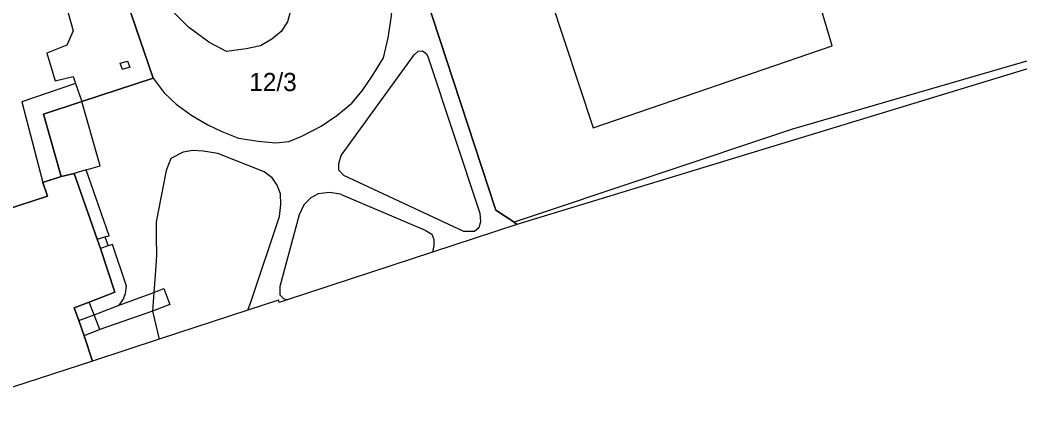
# Model space of a CAD drawing. Extents: x -264070 to -262271, y -1238894 to -1238141.
# Drawn here: x -263238.5 to -263128.8, y -1238889.7 to -1238845.2 of the extents above; entities that cross this region are included whole.
import ezdxf

# ---------------------------------------------------------------- set-up
doc = ezdxf.new("R2010")
doc.units = 0
for name, color, linetype in [('body_kn', 7, 'Continuous'), ('katuz_linie', 7, 'Continuous'), ('kladpar_druhypozemkov', 7, 'Continuous'), ('kladpar_hranice', 7, 'Continuous'), ('kladpar_parcelnecisla', 7, 'Continuous'), ('kladpar_plochy', 7, 'Continuous'), ('linie', 7, 'Continuous'), ('zappar_hrandruhpozemk', 7, 'Continuous'), ('zuob_linie', 7, 'Continuous'), ('zuob_plochy', 7, 'Continuous')]:
    doc.layers.add(name, color=color, linetype=linetype)

msp = doc.modelspace()

# ---------------------------------------------------------------- linework, layer by layer
at = {"layer": 'body_kn'}
for p, q in [((-263209.12, -1238845.39), (-263209.12, -1238845.39)), ((-263232.63, -1238846.39), (-263232.63, -1238846.39)), ((-263219.97, -1238846), (-263219.97, -1238846)), ((-263209.81, -1238846.47), (-263209.81, -1238846.47)), ((-263217.75, -1238847.65), (-263217.75, -1238847.65)), ((-263210.83, -1238847.31), (-263210.83, -1238847.31)), ((-263198.06, -1238847.16), (-263198.06, -1238847.16)), ((-263233.32, -1238847.98), (-263233.32, -1238847.98)), ((-263215.81, -1238848.65), (-263215.81, -1238848.65)), ((-263213.65, -1238848.38), (-263213.65, -1238848.38)), ((-263212.09, -1238848.02), (-263212.09, -1238848.02)), ((-263194.78, -1238848.62), (-263194.78, -1238848.62)), ((-263194.3, -1238848.59), (-263194.3, -1238848.59)), ((-263149.38, -1238848.04), (-263149.38, -1238848.04)), ((-263235.51, -1238848.84), (-263235.51, -1238848.84)), ((-263226.67, -1238849.7), (-263226.67, -1238849.7)), ((-263198.58, -1238849.34), (-263198.58, -1238849.34)), ((-263195.23, -1238849.04), (-263195.23, -1238849.04)), ((-263193.91, -1238848.89), (-263193.91, -1238848.89)), ((-263193.73, -1238849.22), (-263193.73, -1238849.22)), ((-263193.73, -1238849.22), (-263193.73, -1238849.22)), ((-263227.48, -1238849.94), (-263227.48, -1238849.94)), ((-263227.48, -1238849.94), (-263227.48, -1238849.94)), ((-263227.21, -1238850.63), (-263227.21, -1238850.63)), ((-263226.43, -1238850.39), (-263226.43, -1238850.39)), ((-263234.62, -1238851.87), (-263234.62, -1238851.87)), ((-263232.61, -1238851.39), (-263232.61, -1238851.39)), ((-263223.85, -1238851.59), (-263223.85, -1238851.59)), ((-263223.85, -1238851.59), (-263223.85, -1238851.59)), ((-263199.81, -1238851.35), (-263199.81, -1238851.35)), ((-263232.36, -1238852.15), (-263232.36, -1238852.15)), ((-263232.36, -1238852.15), (-263232.36, -1238852.15)), ((-263200.92, -1238852.96), (-263200.92, -1238852.96)), ((-263238.27, -1238854.18), (-263238.27, -1238854.18)), ((-263231.66, -1238854.15), (-263231.66, -1238854.15)), ((-263222.65, -1238853.18), (-263222.65, -1238853.18)), ((-263221.34, -1238854.42), (-263221.34, -1238854.42)), ((-263202.06, -1238854.31), (-263202.06, -1238854.31)), ((-263235.87, -1238855.52), (-263235.87, -1238855.52)), ((-263219.6, -1238855.68), (-263219.6, -1238855.68)), ((-263203.72, -1238855.69), (-263203.72, -1238855.69)), ((-263217.86, -1238856.7), (-263217.86, -1238856.7)), ((-263216.31, -1238857.42), (-263216.31, -1238857.42)), ((-263205.43, -1238856.85), (-263205.43, -1238856.85)), ((-263175.6, -1238857.01), (-263175.6, -1238857.01)), ((-263153.7, -1238857.16), (-263153.7, -1238857.16)), ((-263214.48, -1238858.15), (-263214.48, -1238858.15)), ((-263212.32, -1238858.48), (-263212.32, -1238858.48)), ((-263208.97, -1238858.52), (-263208.97, -1238858.52)), ((-263207.56, -1238857.95), (-263207.56, -1238857.95)), ((-263220.55, -1238859.71), (-263220.55, -1238859.71)), ((-263219.5, -1238859.51), (-263219.5, -1238859.51)), ((-263218.36, -1238859.57), (-263218.36, -1238859.57)), ((-263210.38, -1238858.67), (-263210.38, -1238858.67)), ((-263221.9, -1238860.4), (-263221.9, -1238860.4)), ((-263216.77, -1238859.84), (-263216.77, -1238859.84)), ((-263203.23, -1238860.05), (-263203.23, -1238860.05)), ((-263231.2, -1238861.62), (-263231.2, -1238861.62)), ((-263229.67, -1238861.2), (-263229.67, -1238861.2)), ((-263222.41, -1238861.69), (-263222.41, -1238861.69)), ((-263211.68, -1238861.86), (-263211.68, -1238861.86)), ((-263203.5, -1238860.95), (-263203.5, -1238860.95)), ((-263203.5, -1238861.67), (-263203.5, -1238861.67)), ((-263235.96, -1238863), (-263235.96, -1238863)), ((-263233.93, -1238862.37), (-263233.93, -1238862.37)), ((-263232.51, -1238862.04), (-263232.51, -1238862.04)), ((-263210.78, -1238862.49), (-263210.78, -1238862.49)), ((-263202.93, -1238862.24), (-263202.93, -1238862.24)), ((-263210.25, -1238863.3), (-263210.25, -1238863.3)), ((-263235.45, -1238864.53), (-263235.45, -1238864.53)), ((-263209.89, -1238864.26), (-263209.89, -1238864.26)), ((-263206.56, -1238864.69), (-263206.56, -1238864.69)), ((-263205.75, -1238864.27), (-263205.75, -1238864.27)), ((-263204.52, -1238864.12), (-263204.52, -1238864.12)), ((-263203.3, -1238864.28), (-263203.3, -1238864.28)), ((-263209.83, -1238865.43), (-263209.83, -1238865.43)), ((-263207.31, -1238865.47), (-263207.31, -1238865.47)), ((-263186.27, -1238866.06), (-263186.27, -1238866.06)), ((-263223.53, -1238867.32), (-263223.53, -1238867.32)), ((-263209.98, -1238866.75), (-263209.98, -1238866.75)), ((-263207.83, -1238866.55), (-263207.83, -1238866.55)), ((-263188.02, -1238866.38), (-263188.02, -1238866.38)), ((-263187.93, -1238867.34), (-263187.93, -1238867.34)), ((-263184.24, -1238867.36), (-263184.24, -1238867.36)), ((-263194.02, -1238868.25), (-263194.02, -1238868.25)), ((-263189.76, -1238868.38), (-263189.76, -1238868.38)), ((-263188.59, -1238868.39), (-263188.59, -1238868.39)), ((-263188.14, -1238867.97), (-263188.14, -1238867.97)), ((-263183.95, -1238867.62), (-263183.95, -1238867.62)), ((-263229.98, -1238869.22), (-263229.98, -1238869.22)), ((-263229.98, -1238869.22), (-263229.98, -1238869.22)), ((-263229.14, -1238868.99), (-263229.14, -1238868.99)), ((-263229.14, -1238868.99), (-263229.14, -1238868.99)), ((-263228.67, -1238868.86), (-263228.67, -1238868.86)), ((-263228.67, -1238868.86), (-263228.67, -1238868.86)), ((-263223.54, -1238868.97), (-263223.54, -1238868.97)), ((-263193.3, -1238868.68), (-263193.3, -1238868.68)), ((-263193.06, -1238869.26), (-263193.06, -1238869.26)), ((-263229.63, -1238870.24), (-263229.63, -1238870.24)), ((-263228.79, -1238869.96), (-263228.79, -1238869.96)), ((-263228.79, -1238869.96), (-263228.79, -1238869.96)), ((-263228.32, -1238869.83), (-263228.32, -1238869.83)), ((-263228.32, -1238869.83), (-263228.32, -1238869.83)), ((-263193.2, -1238870.66), (-263193.2, -1238870.66)), ((-263193.07, -1238869.91), (-263193.07, -1238869.91)), ((-263223.48, -1238871.01), (-263223.48, -1238871.01)), ((-263223.63, -1238873.19), (-263223.63, -1238873.19)), ((-263228.04, -1238875.03), (-263228.04, -1238875.03)), ((-263226.76, -1238874.39), (-263226.76, -1238874.39)), ((-263223.78, -1238875.06), (-263223.78, -1238875.06)), ((-263223.78, -1238875.06), (-263223.78, -1238875.06)), ((-263222.67, -1238874.64), (-263222.67, -1238874.64)), ((-263209.94, -1238874.42), (-263209.94, -1238874.42)), ((-263230.89, -1238876.12), (-263230.89, -1238876.12)), ((-263227.16, -1238875.83), (-263227.16, -1238875.83)), ((-263226.89, -1238875.17), (-263226.89, -1238875.17)), ((-263213.09, -1238876.03), (-263213.09, -1238876.03)), ((-263210.09, -1238875.93), (-263210.09, -1238875.93)), ((-263209.94, -1238875.32), (-263209.94, -1238875.32)), ((-263209.55, -1238875.74), (-263209.55, -1238875.74)), ((-263209.16, -1238875.89), (-263209.16, -1238875.89)), ((-263232.51, -1238876.76), (-263232.51, -1238876.76)), ((-263227.58, -1238876.46), (-263227.58, -1238876.46)), ((-263223.93, -1238877.11), (-263223.93, -1238877.11)), ((-263223.93, -1238877.11), (-263223.93, -1238877.11)), ((-263222.01, -1238876.41), (-263222.01, -1238876.41)), ((-263213.45, -1238877.03), (-263213.45, -1238877.03)), ((-263213.45, -1238877.03), (-263213.45, -1238877.03)), ((-263210.03, -1238876.18), (-263210.03, -1238876.18)), ((-263232, -1238878.13), (-263232, -1238878.13)), ((-263232, -1238878.13), (-263232, -1238878.13)), ((-263230.34, -1238877.52), (-263230.34, -1238877.52)), ((-263229.72, -1238879.15), (-263229.72, -1238879.15)), ((-263229.72, -1238879.15), (-263229.72, -1238879.15)), ((-263231.43, -1238879.83), (-263231.43, -1238879.83)), ((-263223.21, -1238880.21), (-263223.21, -1238880.21)), ((-263230.51, -1238882.59), (-263230.51, -1238882.59))]:
    msp.add_line(p, q, dxfattribs=at)
at = {"layer": 'katuz_linie'}
msp.add_lwpolyline([(-263120.72, -1238848.38), (-263183.95, -1238867.62), (-263193.2, -1238870.66), (-263209.16, -1238875.89), (-263210.03, -1238876.18), (-263210.09, -1238875.93), (-263213.45, -1238877.03), (-263223.21, -1238880.21), (-263230.51, -1238882.59), (-263252.36, -1238889.71)], dxfattribs=at)
at = {"layer": 'kladpar_druhypozemkov'}
msp.add_line((-263209.9, -1238851.25), (-263209.9, -1238851.25), dxfattribs=at)
at = {"layer": 'kladpar_hranice'}
for points in [[(-263135.65, -1238796.53), (-263135.5, -1238797.03), (-263120.94, -1238847.64), (-263120.72, -1238848.38), (-263183.95, -1238867.62), (-263184.24, -1238867.36), (-263186.27, -1238866.06), (-263193.99, -1238842.51), (-263187.54, -1238840.14), (-263192.11, -1238828.83), (-263195.56, -1238820.6), (-263177.48, -1238813.26), (-263171.91, -1238810.99), (-263161.5, -1238806.77), (-263135.65, -1238796.53)], [(-263231.14, -1238830.29), (-263223.85, -1238851.59), (-263231.66, -1238854.15), (-263235.87, -1238855.52), (-263233.93, -1238862.37), (-263235.96, -1238863), (-263235.45, -1238864.53), (-263241.78, -1238866.58), (-263242.56, -1238863.97), (-263247.9, -1238865.83), (-263251.88, -1238852.55), (-263253.82, -1238853.14), (-263256.32, -1238853.89), (-263258.04, -1238847.95), (-263255.61, -1238847.11), (-263250.48, -1238845.33), (-263249.59, -1238845.02), (-263252.15, -1238837.32), (-263231.14, -1238830.29)], [(-263193.99, -1238842.51), (-263186.27, -1238866.06), (-263184.24, -1238867.36), (-263183.95, -1238867.62), (-263193.2, -1238870.66), (-263209.16, -1238875.89), (-263210.03, -1238876.18), (-263210.09, -1238875.93), (-263213.45, -1238877.03), (-263223.21, -1238880.21), (-263230.51, -1238882.59), (-263231.43, -1238879.83), (-263232, -1238878.13), (-263232.51, -1238876.76), (-263230.89, -1238876.12), (-263228.04, -1238875.03), (-263229.63, -1238870.24), (-263229.98, -1238869.22), (-263232.51, -1238862.04), (-263233.93, -1238862.37), (-263235.87, -1238855.52), (-263231.66, -1238854.15), (-263223.85, -1238851.59), (-263231.14, -1238830.29)], [(-263241.78, -1238866.58), (-263235.45, -1238864.53), (-263235.96, -1238863), (-263233.93, -1238862.37), (-263232.51, -1238862.04), (-263229.98, -1238869.22), (-263229.63, -1238870.24), (-263228.04, -1238875.03), (-263230.89, -1238876.12), (-263232.51, -1238876.76), (-263232, -1238878.13), (-263231.43, -1238879.83), (-263230.51, -1238882.59), (-263252.36, -1238889.71)]]:
    msp.add_lwpolyline(points, dxfattribs=at)
at = {"layer": 'kladpar_plochy'}
for points in [[(-263135.65, -1238796.53), (-263135.5, -1238797.03), (-263120.94, -1238847.64), (-263120.72, -1238848.38), (-263183.95, -1238867.62), (-263184.24, -1238867.36), (-263186.27, -1238866.06), (-263193.99, -1238842.51), (-263187.54, -1238840.14), (-263192.11, -1238828.83), (-263195.56, -1238820.6), (-263177.48, -1238813.26), (-263171.91, -1238810.99), (-263161.5, -1238806.77)], [(-263231.14, -1238830.29), (-263223.85, -1238851.59), (-263231.66, -1238854.15), (-263235.87, -1238855.52), (-263233.93, -1238862.37), (-263235.96, -1238863), (-263235.45, -1238864.53), (-263241.78, -1238866.58), (-263242.56, -1238863.97), (-263247.9, -1238865.83), (-263251.88, -1238852.55), (-263253.82, -1238853.14), (-263256.32, -1238853.89), (-263258.04, -1238847.95), (-263255.61, -1238847.11), (-263250.48, -1238845.33), (-263249.59, -1238845.02), (-263252.15, -1238837.32)]]:
    msp.add_lwpolyline(points, close=True, dxfattribs=at)
for points in [[(-263193.99, -1238842.51), (-263186.27, -1238866.06), (-263184.24, -1238867.36), (-263183.95, -1238867.62), (-263193.2, -1238870.66), (-263209.16, -1238875.89), (-263210.03, -1238876.18), (-263210.09, -1238875.93), (-263213.45, -1238877.03), (-263223.21, -1238880.21), (-263230.51, -1238882.59), (-263231.43, -1238879.83), (-263232, -1238878.13), (-263232.51, -1238876.76), (-263230.89, -1238876.12), (-263228.04, -1238875.03), (-263229.63, -1238870.24), (-263229.98, -1238869.22), (-263232.51, -1238862.04), (-263233.93, -1238862.37), (-263235.87, -1238855.52), (-263231.66, -1238854.15), (-263223.85, -1238851.59), (-263231.14, -1238830.29)], [(-263241.78, -1238866.58), (-263235.45, -1238864.53), (-263235.96, -1238863), (-263233.93, -1238862.37), (-263232.51, -1238862.04), (-263229.98, -1238869.22), (-263229.63, -1238870.24), (-263228.04, -1238875.03), (-263230.89, -1238876.12), (-263232.51, -1238876.76), (-263232, -1238878.13), (-263231.43, -1238879.83), (-263230.51, -1238882.59), (-263252.36, -1238889.71)]]:
    msp.add_lwpolyline(points, dxfattribs=at)
at = {"layer": 'linie'}
msp.add_lwpolyline([(-263120.72, -1238848.38), (-263183.95, -1238867.62), (-263193.2, -1238870.66), (-263209.16, -1238875.89), (-263210.03, -1238876.18), (-263210.09, -1238875.93), (-263213.45, -1238877.03), (-263223.21, -1238880.21), (-263230.51, -1238882.59), (-263252.36, -1238889.71)], dxfattribs=at)
at = {"layer": 'zappar_hrandruhpozemk'}
for p, q in [((-263149.38, -1238848.04), (-263161.42, -1238806.99)), ((-263234.8, -1238838.71), (-263232.63, -1238846.39)), ((-263181.07, -1238840.42), (-263175.6, -1238857.01)), ((-263120.94, -1238847.64), (-263153.7, -1238857.16)), ((-263175.6, -1238857.01), (-263149.38, -1238848.04)), ((-263203.23, -1238860.05), (-263195.23, -1238849.04)), ((-263227.21, -1238850.63), (-263227.48, -1238849.94)), ((-263232.36, -1238852.15), (-263238.27, -1238854.18)), ((-263238.27, -1238854.18), (-263235.96, -1238863)), ((-263229.67, -1238861.2), (-263231.66, -1238854.15)), ((-263153.7, -1238857.16), (-263184.24, -1238867.36)), ((-263211.68, -1238861.86), (-263216.77, -1238859.84)), ((-263231.2, -1238861.62), (-263232.51, -1238862.04)), ((-263231.2, -1238861.62), (-263229.67, -1238861.2)), ((-263228.67, -1238868.86), (-263231.2, -1238861.62)), ((-263205.75, -1238864.27), (-263206.56, -1238864.69)), ((-263229.14, -1238868.99), (-263228.79, -1238869.96)), ((-263228.79, -1238869.96), (-263229.63, -1238870.24)), ((-263228.32, -1238869.83), (-263228.79, -1238869.96)), ((-263226.76, -1238874.39), (-263228.32, -1238869.83)), ((-263227.58, -1238876.46), (-263223.78, -1238875.06)), ((-263223.78, -1238875.06), (-263222.67, -1238874.64)), ((-263222.67, -1238874.64), (-263222.01, -1238876.41)), ((-263223.93, -1238877.11), (-263229.72, -1238879.15)), ((-263223.93, -1238877.11), (-263223.21, -1238880.21)), ((-263229.72, -1238879.15), (-263231.43, -1238879.83))]:
    msp.add_line(p, q, dxfattribs=at)
for points in [[(-263214.91, -1238835.13), (-263212.93, -1238835.34), (-263211.34, -1238835.74), (-263210.06, -1238836.67), (-263209.31, -1238837.75), (-263208.8, -1238839.4), (-263208.57, -1238841.02), (-263208.45, -1238842.52), (-263208.79, -1238844.2), (-263209.12, -1238845.39), (-263209.81, -1238846.47), (-263210.83, -1238847.31), (-263212.09, -1238848.02), (-263213.65, -1238848.38), (-263215.81, -1238848.65), (-263217.75, -1238847.65), (-263219.97, -1238846), (-263221.52, -1238844.44), (-263223.02, -1238842.73), (-263223.35, -1238841.77), (-263223.4, -1238840.18), (-263222.62, -1238838.35), (-263221.33, -1238836.73), (-263220.13, -1238835.93)], [(-263223.85, -1238851.59), (-263222.65, -1238853.18), (-263221.34, -1238854.42), (-263219.6, -1238855.68), (-263217.86, -1238856.7), (-263216.31, -1238857.42), (-263214.48, -1238858.15), (-263212.32, -1238858.48), (-263210.38, -1238858.67), (-263208.97, -1238858.52), (-263207.56, -1238857.95), (-263205.43, -1238856.85), (-263203.72, -1238855.69), (-263202.06, -1238854.31), (-263200.92, -1238852.96), (-263199.81, -1238851.35), (-263198.58, -1238849.34), (-263198.06, -1238847.16), (-263197.7, -1238844.76), (-263197.48, -1238841.94)], [(-263232.63, -1238846.39), (-263233.32, -1238847.98), (-263235.51, -1238848.84), (-263234.62, -1238851.87), (-263232.61, -1238851.39), (-263232.36, -1238852.15), (-263231.66, -1238854.15)], [(-263195.23, -1238849.04), (-263194.78, -1238848.62), (-263194.3, -1238848.59), (-263193.91, -1238848.89), (-263193.73, -1238849.22)], [(-263227.48, -1238849.94), (-263226.67, -1238849.7), (-263226.43, -1238850.39), (-263227.21, -1238850.63)], [(-263193.73, -1238849.22), (-263188.02, -1238866.38), (-263187.93, -1238867.34), (-263188.14, -1238867.97), (-263188.59, -1238868.39), (-263189.76, -1238868.38), (-263202.93, -1238862.24), (-263203.5, -1238861.67), (-263203.5, -1238860.95), (-263203.23, -1238860.05)], [(-263216.77, -1238859.84), (-263218.36, -1238859.57), (-263219.5, -1238859.51), (-263220.55, -1238859.71), (-263221.9, -1238860.4), (-263222.41, -1238861.69), (-263223.53, -1238867.32), (-263223.54, -1238868.97), (-263223.48, -1238871.01), (-263223.63, -1238873.19), (-263223.78, -1238875.06), (-263223.93, -1238877.11)], [(-263213.45, -1238877.03), (-263213.09, -1238876.03), (-263209.98, -1238866.75), (-263209.83, -1238865.43), (-263209.89, -1238864.26), (-263210.25, -1238863.3), (-263210.78, -1238862.49), (-263211.68, -1238861.86)], [(-263206.56, -1238864.69), (-263207.31, -1238865.47), (-263207.83, -1238866.55), (-263209.94, -1238874.42), (-263209.94, -1238875.32), (-263209.55, -1238875.74), (-263209.16, -1238875.89)], [(-263203.3, -1238864.28), (-263204.52, -1238864.12), (-263205.75, -1238864.27)], [(-263203.3, -1238864.28), (-263194.02, -1238868.25), (-263193.3, -1238868.68), (-263193.06, -1238869.26), (-263193.07, -1238869.91), (-263193.2, -1238870.66)], [(-263229.98, -1238869.22), (-263229.14, -1238868.99), (-263228.67, -1238868.86)], [(-263227.58, -1238876.46), (-263227.16, -1238875.83), (-263226.89, -1238875.17), (-263226.76, -1238874.39)], [(-263229.72, -1238879.15), (-263230.34, -1238877.52), (-263230.89, -1238876.12)], [(-263232, -1238878.13), (-263230.34, -1238877.52), (-263227.58, -1238876.46)], [(-263222.01, -1238876.41), (-263223.93, -1238877.11), (-263229.72, -1238879.15), (-263231.43, -1238879.83)]]:
    msp.add_lwpolyline(points, dxfattribs=at)
at = {"layer": 'zuob_linie'}
msp.add_lwpolyline([(-263120.72, -1238848.38), (-263183.95, -1238867.62), (-263193.2, -1238870.66), (-263209.16, -1238875.89), (-263210.03, -1238876.18), (-263210.09, -1238875.93), (-263213.45, -1238877.03), (-263223.21, -1238880.21), (-263230.51, -1238882.59), (-263252.36, -1238889.71)], dxfattribs=at)
at = {"layer": 'zuob_plochy'}
msp.add_lwpolyline([(-263120.72, -1238848.38), (-263183.95, -1238867.62), (-263193.2, -1238870.66), (-263209.16, -1238875.89), (-263210.03, -1238876.18), (-263210.09, -1238875.93), (-263213.45, -1238877.03), (-263223.21, -1238880.21), (-263230.51, -1238882.59), (-263252.36, -1238889.71)], dxfattribs=at)

# ---------------------------------------------------------------- texts
at = {"layer": 'kladpar_parcelnecisla'}
msp.add_text('12/3', height=2, dxfattribs=at).set_placement((-263213.31, -1238853))

doc.saveas('drawing.dxf')
